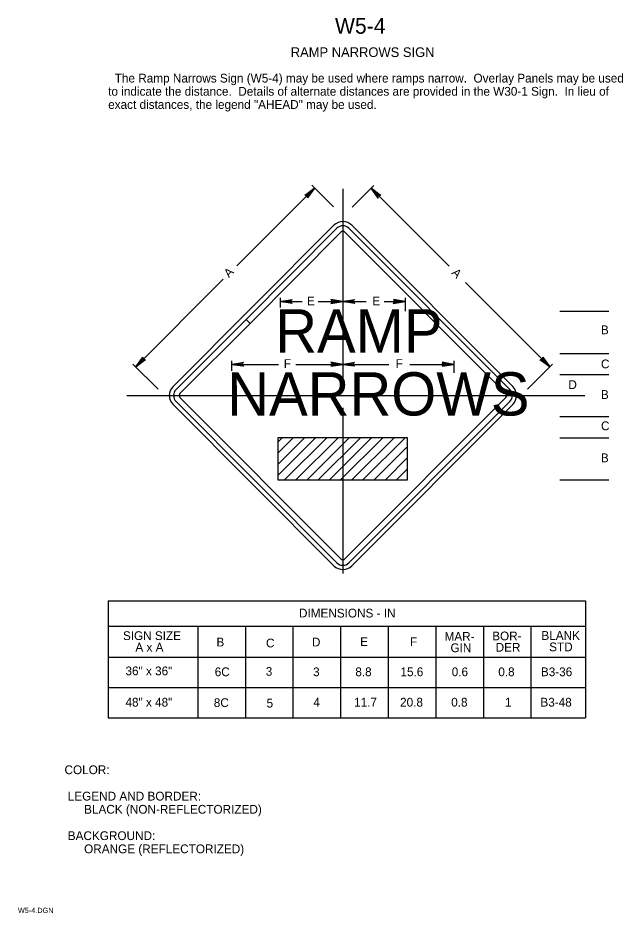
# Model space of a CAD drawing. Extents: x 0.013 to 0.185, y 0.004 to 0.259.
import ezdxf

# ---------------------------------------------------------------- set-up
doc = ezdxf.new("R2010")
doc.units = 0
for name, color, linetype in [('1', 7, 'Continuous'), ('2', 7, 'Continuous'), ('3', 7, 'Continuous')]:
    doc.layers.add(name, color=color, linetype=linetype)

# ---------------------------------------------------------------- blocks, each defined once
blk = doc.blocks.new('RARROW')
at = {"layer": '3'}
for p, q in [((-2.156, 0.28500000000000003), (-2.2665, 0.384625)), ((-2.2665, 0.384625), (0, 0)), ((0, 0), (-2.2665, -0.379125)), ((-2.156, 0.28500000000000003), (-2.075625, 0.12075)), ((0, 0), (-2.156, 0.28500000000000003)), ((-2.14975, -0.2705), (0, 0)), ((-2.075625, 0.12075), (0, 0)), ((0, 0), (-2.074, -0.108)), ((-2.2665, -0.379125), (-2.14975, -0.2705)), ((-2.074, -0.108), (-2.14975, -0.2705))]:
    blk.add_line(p, q, dxfattribs=at)

msp = doc.modelspace()

# ---------------------------------------------------------------- linework, layer by layer
at = {"layer": '1'}
for p, q in [((0.10234647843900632, 0.2000063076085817), (0.05659639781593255, 0.15411502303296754)), ((0.10319629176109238, 0.19915910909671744), (0.07736178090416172, 0.1732448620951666)), ((0.1523457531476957, 0.15326782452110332), (0.10659567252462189, 0.19915910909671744)), ((0.15319556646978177, 0.15411502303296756), (0.10744548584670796, 0.2000063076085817)), ((0.07849142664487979, 0.17211172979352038), (0.1043294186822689, 0.19802946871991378)), ((0.10546254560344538, 0.19802946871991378), (0.15121262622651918, 0.1521381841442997)), ((0.08708273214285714, 0.17933392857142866), (0.08708273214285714, 0.17661785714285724)), ((0.08708273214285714, 0.17828955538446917), (0.0933153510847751, 0.17828955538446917)), ((0.09781814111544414, 0.17828955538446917), (0.10483973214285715, 0.17828955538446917)), ((0.10483973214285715, 0.17828955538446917), (0.11152663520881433, 0.17828955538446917)), ((0.11662979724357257, 0.17828955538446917), (0.12259673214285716, 0.17828955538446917)), ((0.12259673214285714, 0.17933392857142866), (0.12259673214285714, 0.1755831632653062)), ((0.07736178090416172, 0.1732448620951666), (0.05744621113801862, 0.15326782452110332)), ((0.07736178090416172, 0.1732448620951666), (0.07849142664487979, 0.17211172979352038)), ((0.07849142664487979, 0.17211172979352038), (0.07736178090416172, 0.1732448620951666)), ((0.16655218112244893, 0.17557348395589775), (0.18052054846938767, 0.17557348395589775)), ((0.058579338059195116, 0.15213818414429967), (0.07849142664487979, 0.17211172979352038)), ((0.16655218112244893, 0.16357342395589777), (0.18052054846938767, 0.16357342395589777)), ((0.07323974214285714, 0.16148545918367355), (0.07323974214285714, 0.15864005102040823)), ((0.07323974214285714, 0.16044108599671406), (0.0866111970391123, 0.16044108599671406)), ((0.09151423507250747, 0.16044108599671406), (0.10483973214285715, 0.16044108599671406)), ((0.10483973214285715, 0.16044108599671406), (0.11793060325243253, 0.16044108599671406)), ((0.12393432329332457, 0.16044108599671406), (0.13643972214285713, 0.16044108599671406)), ((0.13643972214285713, 0.16148545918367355), (0.13643972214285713, 0.15799336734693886)), ((0.16655218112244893, 0.15757339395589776), (0.18052054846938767, 0.15757339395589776)), ((0.10432941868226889, 0.10511725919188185), (0.058579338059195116, 0.151008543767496)), ((0.15121262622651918, 0.15100854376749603), (0.10546254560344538, 0.10511725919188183)), ((0.10234647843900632, 0.10314042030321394), (0.056596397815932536, 0.1490317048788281)), ((0.05744621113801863, 0.14987890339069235), (0.10319629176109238, 0.10398761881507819)), ((0.10659567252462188, 0.10398761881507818), (0.15234575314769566, 0.1498789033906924)), ((0.15319556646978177, 0.1490317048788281), (0.10744548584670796, 0.10314042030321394)), ((0.16655218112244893, 0.1455733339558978), (0.18052054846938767, 0.1455733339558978)), ((0.0863843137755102, 0.13836155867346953), (0.08759605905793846, 0.1395733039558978)), ((0.0863843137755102, 0.1351795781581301), (0.09077803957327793, 0.1395733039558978)), ((0.0863843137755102, 0.1319975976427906), (0.0939600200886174, 0.1395733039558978)), ((0.0863843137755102, 0.1288156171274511), (0.09714200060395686, 0.1395733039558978)), ((0.08832392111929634, 0.1275732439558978), (0.10032398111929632, 0.1395733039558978)), ((0.0915059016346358, 0.1275732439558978), (0.10350596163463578, 0.1395733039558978)), ((0.09468788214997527, 0.1275732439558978), (0.10668794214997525, 0.1395733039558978)), ((0.09786986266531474, 0.1275732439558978), (0.10986992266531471, 0.1395733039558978)), ((0.10105184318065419, 0.1275732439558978), (0.11305190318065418, 0.1395733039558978)), ((0.10423382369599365, 0.1275732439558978), (0.11623388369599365, 0.1395733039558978)), ((0.10741580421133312, 0.1275732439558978), (0.1194158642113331, 0.1395733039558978)), ((0.11059778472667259, 0.1275732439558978), (0.12259784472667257, 0.1395733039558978)), ((0.16655218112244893, 0.1395733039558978), (0.18052054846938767, 0.1395733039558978)), ((0.11377976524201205, 0.1275732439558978), (0.12329515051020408, 0.13708862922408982)), ((0.1169617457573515, 0.1275732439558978), (0.12329515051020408, 0.13390664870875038)), ((0.12014372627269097, 0.1275732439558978), (0.12329515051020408, 0.13072466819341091)), ((0.16655218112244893, 0.1275732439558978), (0.18052054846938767, 0.1275732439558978))]:
    msp.add_line(p, q, dxfattribs=at)
msp.add_lwpolyline([(0.0863843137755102, 0.1275732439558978), (0.12329515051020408, 0.1275732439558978), (0.12329515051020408, 0.1395733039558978), (0.0863843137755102, 0.1395733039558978)], close=True, dxfattribs=at)
for centre, radius, start, end in [((0.10489598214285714, 0.19746464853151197), 0.0036000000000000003, 44.911716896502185, 135.08828310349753), ((0.10489598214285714, 0.19746464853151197), 0.002400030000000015, 44.91171689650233, 135.0882831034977), ((0.10489598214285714, 0.19746464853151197), 0.0008000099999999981, 44.91171689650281, 135.08828310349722), ((0.05914590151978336, 0.15157336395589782), 0.0036000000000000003, 135.08828310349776, 224.91171689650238), ((0.05914590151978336, 0.15157336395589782), 0.00240003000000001, 135.08828310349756, 224.91171689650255), ((0.15064606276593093, 0.15157336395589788), 0.0024000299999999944, 315.0882831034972, 44.911716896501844), ((0.15064606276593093, 0.15157336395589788), 0.0036000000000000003, 315.08828310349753, 44.91171689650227), ((0.05914590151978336, 0.15157336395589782), 0.0008000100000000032, 135.08828310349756, 224.91171689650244), ((0.15064606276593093, 0.15157336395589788), 0.0008000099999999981, 315.0882831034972, 44.91171689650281), ((0.10489598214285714, 0.10568207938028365), 0.0008000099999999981, 224.91171689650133, 315.0882831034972), ((0.10489598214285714, 0.10568207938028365), 0.0036000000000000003, 224.91171689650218, 315.08828310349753), ((0.10489598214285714, 0.10568207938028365), 0.0024000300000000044, 224.91171689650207, 315.0882831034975)]:
    msp.add_arc(centre, radius, start, end, dxfattribs=at)
at = {"layer": '3'}
for p, q in [((0.10219681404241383, 0.20524141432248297), (0.09604985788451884, 0.21138837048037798)), ((0.07473003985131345, 0.1884775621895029), (0.09684535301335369, 0.2105928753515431)), ((0.10483973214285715, 0.2103747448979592), (0.10483973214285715, 0.15599641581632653)), ((0.10753823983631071, 0.20518582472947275), (0.1136851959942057, 0.21133278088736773)), ((0.13508465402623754, 0.1883423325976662), (0.11288970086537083, 0.21053728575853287)), ((0.0708887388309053, 0.18463626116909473), (0.045999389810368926, 0.15974691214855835)), ((0.13974077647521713, 0.18368621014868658), (0.16368007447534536, 0.15974691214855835)), ((0.05236335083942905, 0.1533829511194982), (0.04520389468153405, 0.16054240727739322)), ((0.15731611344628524, 0.1533829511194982), (0.16447556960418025, 0.16054240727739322)), ((0.0434688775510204, 0.15157336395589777), (0.17361510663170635, 0.15157336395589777)), ((0.10483973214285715, 0.14812141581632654), (0.10483973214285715, 0.10098391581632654)), ((0.03817919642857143, 0.09315691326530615), (0.03817919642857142, 0.05988816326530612)), ((0.03817919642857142, 0.09315691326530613), (0.17385586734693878, 0.09315691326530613)), ((0.17385586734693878, 0.09315691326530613), (0.17385586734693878, 0.05988816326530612)), ((0.17385586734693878, 0.08585691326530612), (0.03817919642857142, 0.08585691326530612)), ((0.06363047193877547, 0.08585691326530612), (0.06363047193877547, 0.05988816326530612)), ((0.0771617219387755, 0.08585691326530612), (0.0771617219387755, 0.05988816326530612)), ((0.0906929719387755, 0.08585691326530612), (0.0906929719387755, 0.05988816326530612)), ((0.10422422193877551, 0.08585691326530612), (0.10422422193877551, 0.05988816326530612)), ((0.1177554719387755, 0.08585691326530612), (0.1177554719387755, 0.05988816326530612)), ((0.13128672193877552, 0.08585691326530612), (0.13128672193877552, 0.05988816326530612)), ((0.14481797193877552, 0.08585691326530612), (0.14481797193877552, 0.05988816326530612)), ((0.15834922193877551, 0.08585691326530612), (0.15834922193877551, 0.05988816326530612)), ((0.03817919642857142, 0.07711316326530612), (0.17385586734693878, 0.07711316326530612)), ((0.03817919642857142, 0.06850066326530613), (0.17385586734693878, 0.06850066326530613)), ((0.03817919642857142, 0.05988816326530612), (0.17385586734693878, 0.05988816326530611))]:
    msp.add_line(p, q, dxfattribs=at)

# ---------------------------------------------------------------- block references
for p, xscale, yscale, rotation in [((0.09684535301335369, 0.2105928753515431), 0.0014890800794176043, 0.0014729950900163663, 44.999999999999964), ((0.11288970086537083, 0.21053728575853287), 0.0014890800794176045, 0.001472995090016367, 135), ((0.08708273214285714, 0.17828955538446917), 0.0014890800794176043, 0.0014729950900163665, -179.3867317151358), ((0.10483973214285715, 0.17828955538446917), 0.0014890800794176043, -0.0014729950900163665, -0.6132682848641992), ((0.10483973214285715, 0.17828955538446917), 0.0014890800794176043, 0.0014729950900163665, -179.3867317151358), ((0.12259673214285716, 0.17828955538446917), 0.0014890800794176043, -0.0014729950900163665, -0.6132682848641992), ((0.045999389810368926, 0.15974691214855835), 0.0014890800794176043, 0.0014729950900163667, -135.00000000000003), ((0.07323974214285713, 0.16044108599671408), 0.0014890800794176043, 0.0014729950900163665, -179.3867317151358), ((0.10483973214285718, 0.16044108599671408), 0.0014890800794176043, -0.0014729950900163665, -0.6132682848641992), ((0.10483973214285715, 0.16044108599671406), 0.0014890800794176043, 0.0014729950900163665, -179.3867317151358), ((0.13643972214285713, 0.16044108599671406), 0.0014890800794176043, -0.0014729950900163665, -0.6132682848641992), ((0.16368007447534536, 0.15974691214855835), 0.0014890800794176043, 0.0014729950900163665, -45)]:
    msp.add_blockref('RARROW', p, dxfattribs=dict(at, xscale=xscale, yscale=yscale, rotation=rotation))

# ---------------------------------------------------------------- texts
at = {"layer": '1'}
for s, height, p in [('W5-4', 0.0045000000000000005, (0.10263068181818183, 0.2545)), ('RAMP NARROWS SIGN', 0.00275025, (0.09006642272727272, 0.247875)), ('E', 0.0025, (0.09466494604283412, 0.1772297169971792)), ('E', 0.0025, (0.1132448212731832, 0.1772297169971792)), ('RAMP', 0.012298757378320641, (0.08566294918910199, 0.1638183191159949)), ('B', 0.0025, (0.17823041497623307, 0.1690246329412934)), ('F', 0.0025, (0.08809305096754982, 0.1594186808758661)), ('F', 0.0025, (0.1198811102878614, 0.1594186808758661)), ('C', 0.0025, (0.17825465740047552, 0.15931902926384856)), ('NARROWS', 0.012298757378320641, (0.07203504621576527, 0.14589224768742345)), ('D', 0.0025, (0.16897736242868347, 0.15341496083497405)), ('B', 0.0025, (0.17823041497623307, 0.1506132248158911)), ('C', 0.0025, (0.17825465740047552, 0.14170811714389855)), ('B', 0.0025, (0.17823041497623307, 0.13260206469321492)), ('COLOR:', 0.0024997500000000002, (0.025750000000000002, 0.043874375)), (' LEGEND AND BORDER:', 0.0024997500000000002, (0.025750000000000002, 0.036374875)), ('      BLACK (NON-REFLECTORIZED)', 0.0024997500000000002, (0.025750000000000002, 0.032625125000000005)), (' BACKGROUND:', 0.0024997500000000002, (0.025750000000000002, 0.025125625)), ('      ORANGE (REFLECTORIZED)', 0.0024997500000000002, (0.025750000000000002, 0.021375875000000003)), ('W5-4.DGN', 0.0015, (0.0125, 0.004375))]:
    msp.add_text(s, height=height, dxfattribs=at).set_placement(p)
at = {"layer": '2'}
for s, p in [('  The Ramp Narrows Sign (W5-4) may be used where ramps narrow.  Overlay Panels may be used', (0.038166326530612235, 0.24061657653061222)), ('to indicate the distance.  Details of alternate distances are provided in the W30-1 Sign.  In lieu of', (0.038166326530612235, 0.2368668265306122)), ('exact distances, the legend "AHEAD" may be used.', (0.038166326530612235, 0.2331170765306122))]:
    msp.add_text(s, height=0.0024997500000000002, dxfattribs=at).set_placement(p)
at = {"layer": '3'}
for s, height, rotation, p in [('A', 0.0025, 45, (0.07250238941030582, 0.18494775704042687)), ('A', 0.0025, 315, (0.13559219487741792, 0.18629983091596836)), ('DIMENSIONS - IN', 0.0024940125, 360, (0.09241193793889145, 0.08844709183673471)), ('BLANK', 0.0024940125, 360, (0.1613220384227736, 0.08207241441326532)), ('STD', 0.0024940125, 360, (0.1635330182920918, 0.07882840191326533)), ('0.6', 0.0024940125, 360, (0.13582480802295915, 0.07174128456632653)), ('0.8', 0.0024940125, 360, (0.13567995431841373, 0.06309409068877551))]:
    msp.add_text(s, height=height, rotation=rotation, dxfattribs=at).set_placement(p)
for s, p in [('SIGN SIZE', (0.04236389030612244, 0.08202732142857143)), ('MAR-', (0.13379058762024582, 0.08181374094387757)), ('BOR-', (0.14733144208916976, 0.08194307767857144)), ('B', (0.06894450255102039, 0.08019173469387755)), ('C', (0.08303723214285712, 0.07993497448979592)), ('D', (0.09609335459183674, 0.08019173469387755)), ('E', (0.10979807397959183, 0.08032107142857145)), ('F', (0.12397953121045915, 0.08032107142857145)), ('A x A', (0.04590764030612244, 0.07874607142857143)), ('GIN', (0.13547404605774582, 0.07856972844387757)), ('DER', (0.14831393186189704, 0.07869906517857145)), ('36" x 36"', (0.04308564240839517, 0.07199995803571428)), ('6C', (0.0684553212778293, 0.07174128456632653)), ('3', (0.0829673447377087, 0.07187062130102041)), ('3', (0.09641147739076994, 0.07174128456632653)), ('8.8', (0.10841911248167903, 0.07174128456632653)), ('15.6', (0.12125425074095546, 0.07174128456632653)), ('0.8', (0.14905890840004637, 0.07174128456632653)), ('B3-36', (0.1611765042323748, 0.07174128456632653)), ('48" x 48"', (0.04308564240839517, 0.06309409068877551)), ('8C', (0.06819664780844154, 0.06296666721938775)), ('5', (0.08319850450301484, 0.06283541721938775)), ('4', (0.0964943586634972, 0.06309409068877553)), ('11.7', (0.10807234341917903, 0.06309409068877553)), ('20.8', (0.12114516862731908, 0.06309409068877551)), ('1', (0.15093672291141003, 0.06309409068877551)), ('B3-48', (0.16103547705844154, 0.06309409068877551))]:
    msp.add_text(s, height=0.0024940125, dxfattribs=at).set_placement(p)

doc.saveas('drawing.dxf')
